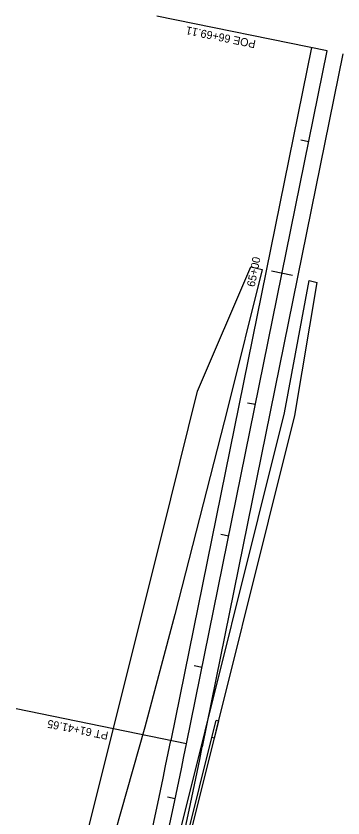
# Model space of a CAD drawing. Extents: x 1445610 to 1446352, y 2042797 to 2056486.
# Drawn here: x 1446108 to 1446352, y 2055888 to 2056486 of the extents above; entities that cross this region are included whole.
import ezdxf

# ---------------------------------------------------------------- set-up
doc = ezdxf.new("R2010")
doc.units = 0
for name, color, linetype in [('20', 7, 'Continuous'), ('MOT_Barrier Wall', 7, 'Continuous'), ('R_Horz Alg', 7, 'Continuous'), ('R_Horz Alg Annot_Detour', 7, 'Continuous'), ('R_Horz Alg Stationing_Detour', 7, 'Continuous'), ('R_Proposed Road', 7, 'Continuous')]:
    doc.layers.add(name, color=color, linetype=linetype)

msp = doc.modelspace()

# ---------------------------------------------------------------- linework, layer by layer
at = {"layer": '20'}
msp.add_lwpolyline([(1446160.91, 2055875.76), (1446223.23, 2056125.73), (1446243.22, 2056205.88), (1446283.12, 2056298.78), (1446291.6, 2056296.75), (1446265.86, 2056193.88), (1446226.35, 2056039.44), (1446204, 2055955.28), (1446163.78, 2055814.06)], dxfattribs=at)
at = {"layer": 'MOT_Barrier Wall'}
for p, q in [((1446254.08, 2055947.71), (1446257.23, 2055960.33)), ((1446256.02, 2055947.23), (1446259.17, 2055959.84)), ((1446259.17, 2055959.84), (1446257.23, 2055960.33)), ((1446219.86, 2055810.7), (1446254.08, 2055947.71)), ((1446221.81, 2055810.26), (1446256.02, 2055947.23)), ((1446256.02, 2055947.23), (1446254.08, 2055947.71))]:
    msp.add_line(p, q, dxfattribs=at)
at = {"layer": 'R_Horz Alg'}
msp.add_line((1446235.07, 2055942.97), (1446340.23, 2056459.85), dxfattribs=at)
msp.add_arc((1440620.51, 2057085.26), 5729.58, 345.4304, 348.5, dxfattribs=at)
at = {"layer": 'R_Horz Alg Annot_Detour'}
for points in [[(1446340.23, 2056459.85), (1446212.84, 2056485.76)], [(1446235.07, 2055942.97), (1446107.67, 2055968.89)]]:
    msp.add_lwpolyline(points, dxfattribs=at)
at = {"layer": 'R_Horz Alg Stationing_Detour'}
for points in [[(1446320.57, 2056393.32), (1446326.45, 2056392.12)], [(1446298.67, 2056295.72), (1446314.35, 2056292.53)], [(1446280.69, 2056197.33), (1446286.57, 2056196.14)], [(1446260.76, 2056099.34), (1446266.64, 2056098.14)], [(1446240.82, 2056001.35), (1446246.7, 2056000.15)], [(1446220.74, 2055903.43), (1446226.61, 2055902.19)]]:
    msp.add_lwpolyline(points, dxfattribs=at)
at = {"layer": 'R_Proposed Road'}
for p, q in [((1446328.47, 2056462.24), (1446223.31, 2055945.36)), ((1446351.98, 2056457.45), (1446246.82, 2055940.58)), ((1446308.23, 2056189.67), (1446326.65, 2056288.39)), ((1446315.99, 2056187.74), (1446332.57, 2056286.97)), ((1446326.65, 2056288.39), (1446332.57, 2056286.97)), ((1446226.97, 2055863.77), (1446308.23, 2056189.67)), ((1446234.73, 2055861.84), (1446315.99, 2056187.74))]:
    msp.add_line(p, q, dxfattribs=at)
for radius, start in [(5717.58, 345.4304), (5741.58, 345.430397)]:
    msp.add_arc((1440620.51, 2057085.26), radius, start, 348.5, dxfattribs=at)

# ---------------------------------------------------------------- texts
at = {"layer": 'R_Horz Alg Annot_Detour'}
for s, p in [('POE 66+69.11', (1446287.2, 2056467.57)), ('PT 61+41.65', (1446177.01, 2055951.72))]:
    msp.add_text(s, height=6, rotation=168.5, dxfattribs=at).set_placement(p)
at = {"layer": 'R_Horz Alg Stationing_Detour'}
msp.add_text('65+00', height=6, rotation=78.5, dxfattribs=at).set_placement((1446285.95, 2056283.37))

doc.saveas('drawing.dxf')
